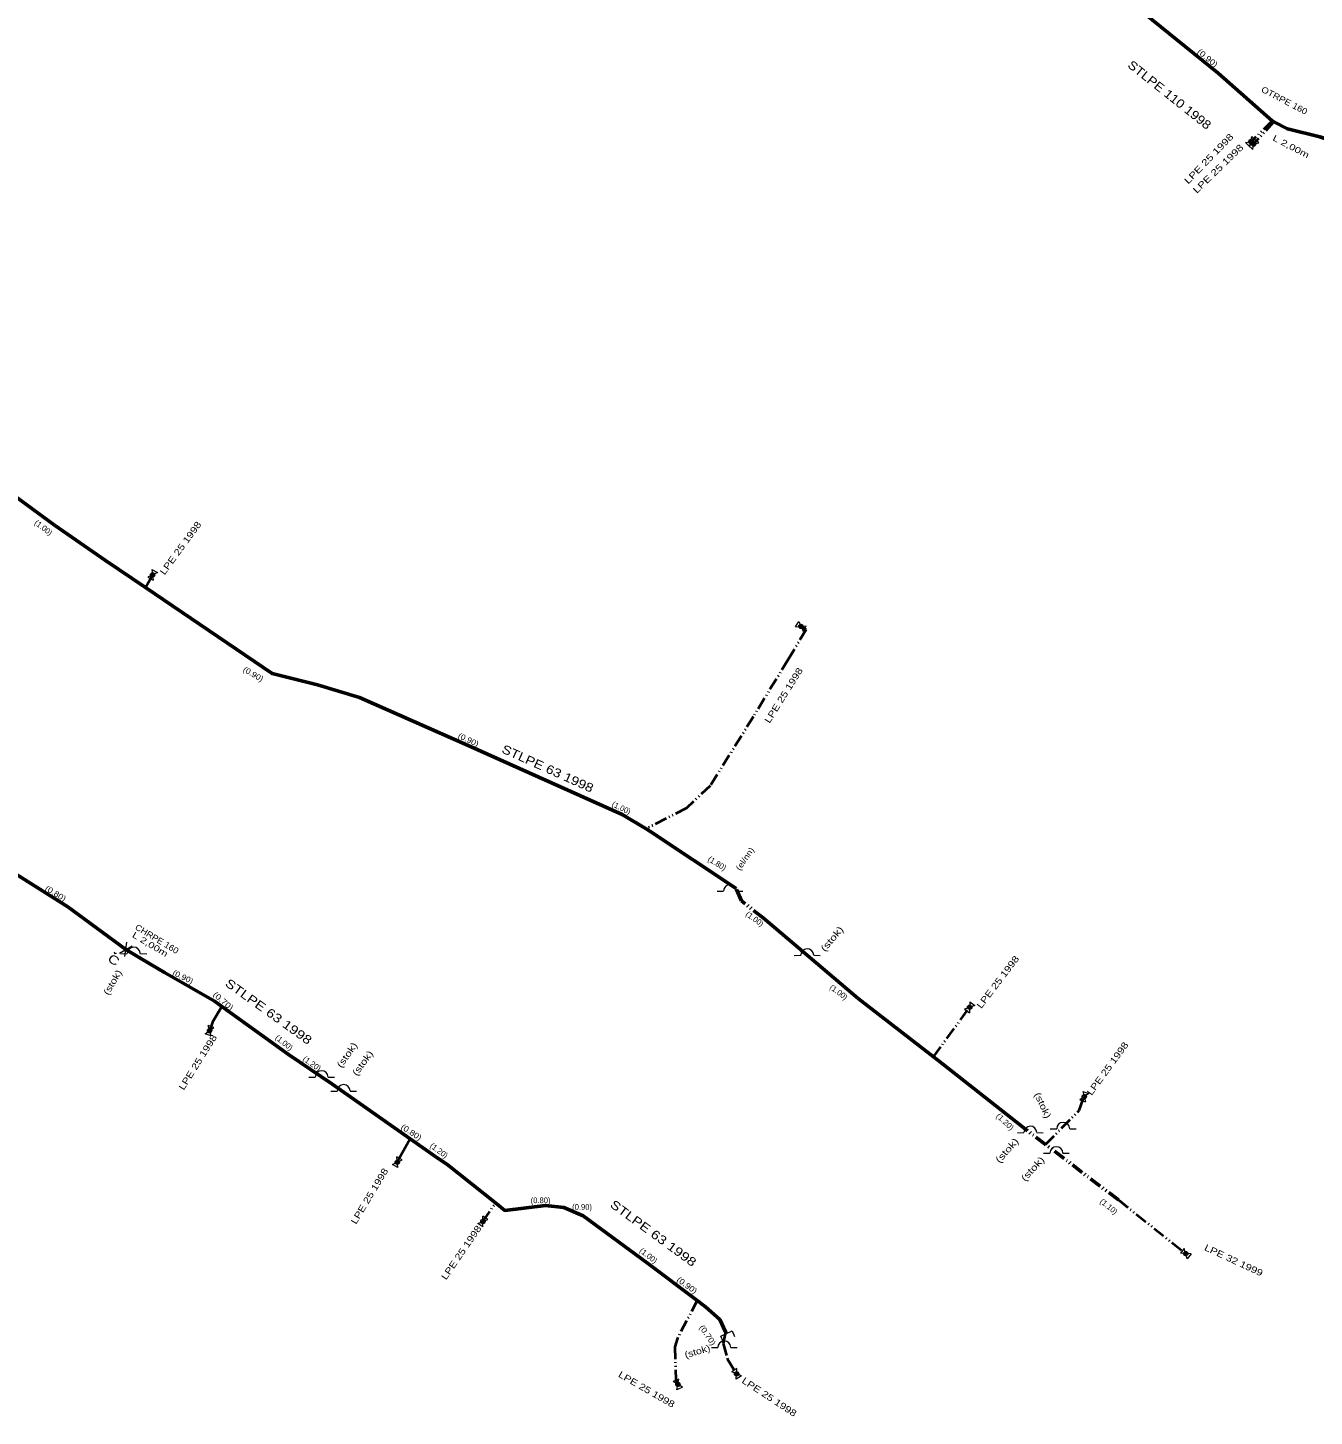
# Model space of a CAD drawing. Extents: x -648036 to -642998, y -1161549 to -1158141.
# Drawn here: x -646338.6 to -646191.3, y -1161129.2 to -1160970.1 of the extents above; entities that cross this region are included whole.
import ezdxf
from ezdxf.enums import TextEntityAlignment as Align

# ---------------------------------------------------------------- set-up
doc = ezdxf.new("R2010")
doc.units = 0
doc.header["$LTSCALE"] = 0.28
doc.linetypes.add('DASH_DOUBLE_DOT', pattern=[9.2, 5, -1.2, 0.3, -1.2, 0.3, -1.2])
for name, color, linetype, lineweight in [('12', 7, 'DASH_DOUBLE_DOT', 40), ('14', 7, 'Continuous', 13), ('15', 7, 'Continuous', 13), ('19', 7, 'Continuous', 13), ('8', 7, 'Continuous', 53)]:
    doc.layers.add(name, color=color, linetype=linetype, lineweight=lineweight)
for name, color, linetype in [('20', 7, 'Continuous'), ('22', 7, 'Continuous'), ('24', 7, 'Continuous'), ('27', 7, 'Continuous'), ('28', 7, 'Continuous')]:
    doc.layers.add(name, color=color, linetype=linetype)

msp = doc.modelspace()

# ---------------------------------------------------------------- linework, layer by layer
at = {"layer": '12'}
for p, q in [((-646196.11, -1160980.79), (-646198.56, -1160983.17)), ((-646195.92, -1160980.89), (-646198.25, -1160983.45)), ((-646325.14, -1161034.26), (-646324.34, -1161032.82)), ((-646234.91, -1161088.02), (-646230.76, -1161082.36)), ((-646213.73, -1161104.44), (-646206.014, -1161110.585)), ((-646286.51, -1161106.9), (-646285.07, -1161104.78))]:
    msp.add_line(p, q, dxfattribs=at)
at = {"layer": '12', "linetype": 'Continuous'}
msp.add_line((-646294.82, -1161097.43), (-646296.31, -1161100.11), dxfattribs=at)
at = {"layer": '12'}
for points in [[(-646250.09, -1161038.71), (-646249.49, -1161039.07), (-646251.54, -1161042.5), (-646255.53, -1161049.04), (-646260.48, -1161056.99), (-646263.2, -1161059.53), (-646267.8, -1161061.91)], [(-646222.06, -1161098.08), (-646218.24, -1161094.19), (-646217.64, -1161092.6)], [(-646261.97, -1161115.97), (-646264.21, -1161120.27), (-646264.52, -1161121.28), (-646264.43, -1161125), (-646264.18, -1161125.57)], [(-646258.71, -1161119.54), (-646258.98, -1161120.89), (-646258.49, -1161122.66), (-646257.45, -1161124.36)]]:
    msp.add_lwpolyline(points, dxfattribs=at)
at = {"layer": '12', "linetype": 'Continuous'}
msp.add_lwpolyline([(-646316.39, -1161082.26), (-646317.47, -1161084.05), (-646317.8, -1161085.05)], dxfattribs=at)
at = {"layer": '14'}
for p, q in [((-646196.11, -1160980.79), (-646194.37, -1160981.71)), ((-646257.52, -1161068.75), (-646267.37, -1161062.17)), ((-646325.67, -1161076.75), (-646327.39, -1161075.72))]:
    msp.add_line(p, q, dxfattribs=at)
at = {"layer": '15'}
for p, q in [((-646199.17, -1160983.266), (-646197.951, -1160983.075)), ((-646198.673, -1160983.777), (-646199.17, -1160983.266)), ((-646198.853, -1160983.583), (-646197.648, -1160983.318)), ((-646198.326, -1160984.062), (-646198.853, -1160983.583)), ((-646198.673, -1160983.777), (-646198.447, -1160982.563)), ((-646197.951, -1160983.075), (-646198.447, -1160982.563)), ((-646198.326, -1160984.062), (-646198.174, -1160982.838)), ((-646197.648, -1160983.318), (-646198.174, -1160982.838)), ((-646323.784, -1161032.552), (-646324.895, -1161033.087)), ((-646324.406, -1161032.207), (-646324.274, -1161033.433)), ((-646324.406, -1161032.207), (-646323.784, -1161032.552)), ((-646324.895, -1161033.087), (-646324.274, -1161033.433)), ((-646250.705, -1161038.756), (-646250.339, -1161038.145)), ((-646250.705, -1161038.756), (-646249.475, -1161038.664)), ((-646250.339, -1161038.145), (-646249.842, -1161039.274)), ((-646249.842, -1161039.274), (-646249.475, -1161038.664)), ((-646259.675, -1161069.035), (-646258.94, -1161069.034)), ((-646257.454, -1161069.034), (-646256.72, -1161069.035)), ((-646328.723, -1161076.01), (-646328.671, -1161076.224)), ((-646328.117, -1161076.14), (-646326.664, -1161075.301)), ((-646327.497, -1161076.552), (-646327.284, -1161074.889)), ((-646328.454, -1161076.18), (-646328.671, -1161076.224)), ((-646327.965, -1161076.215), (-646327.23, -1161076.214)), ((-646325.744, -1161076.214), (-646325.01, -1161076.215)), ((-646250.845, -1161076.405), (-646250.11, -1161076.404)), ((-646248.624, -1161076.404), (-646247.89, -1161076.405)), ((-646230.175, -1161082.164), (-646231.345, -1161082.555)), ((-646230.749, -1161081.743), (-646230.771, -1161082.977)), ((-646230.749, -1161081.743), (-646230.175, -1161082.164)), ((-646231.345, -1161082.555), (-646230.771, -1161082.977)), ((-646318.296, -1161085.417), (-646317.304, -1161084.684)), ((-646317.62, -1161085.64), (-646318.296, -1161085.417)), ((-646317.304, -1161084.684), (-646317.98, -1161084.46)), ((-646317.62, -1161085.64), (-646317.98, -1161084.46)), ((-646306.445, -1161090.365), (-646305.71, -1161090.364)), ((-646304.224, -1161090.364), (-646303.49, -1161090.365)), ((-646303.925, -1161091.965), (-646303.19, -1161091.964)), ((-646301.704, -1161091.964), (-646300.97, -1161091.965)), ((-646217.129, -1161092.254), (-646218.151, -1161092.945)), ((-646218.151, -1161092.945), (-646217.485, -1161093.197)), ((-646217.795, -1161092.003), (-646217.485, -1161093.197)), ((-646217.795, -1161092.003), (-646217.129, -1161092.254)), ((-646221.525, -1161096.285), (-646220.79, -1161096.284)), ((-646219.304, -1161096.284), (-646218.57, -1161096.285)), ((-646225.285, -1161096.725), (-646224.55, -1161096.724)), ((-646223.064, -1161096.724), (-646222.33, -1161096.725)), ((-646296.866, -1161100.378), (-646295.754, -1161099.843)), ((-646295.754, -1161099.843), (-646296.376, -1161099.497)), ((-646296.244, -1161100.723), (-646296.376, -1161099.497)), ((-646222.305, -1161099.075), (-646221.57, -1161099.074)), ((-646220.084, -1161099.074), (-646219.35, -1161099.075)), ((-646296.244, -1161100.723), (-646296.866, -1161100.378)), ((-646287.088, -1161107.117), (-646285.933, -1161106.684)), ((-646286.499, -1161107.517), (-646287.088, -1161107.117)), ((-646285.933, -1161106.684), (-646286.521, -1161106.283)), ((-646286.499, -1161107.517), (-646286.521, -1161106.283)), ((-646206.186, -1161109.993), (-646206.63, -1161110.549)), ((-646205.398, -1161110.621), (-646206.63, -1161110.549)), ((-646205.842, -1161111.177), (-646206.186, -1161109.993)), ((-646205.398, -1161110.621), (-646205.842, -1161111.177)), ((-646260.345, -1161121.355), (-646259.61, -1161121.354)), ((-646258.124, -1161121.354), (-646257.39, -1161121.355)), ((-646264.056, -1161124.966), (-646264.708, -1161125.251)), ((-646263.652, -1161125.889), (-646264.708, -1161125.251)), ((-646264.304, -1161126.175), (-646264.056, -1161124.966)), ((-646257.409, -1161123.745), (-646258.017, -1161124.116)), ((-646256.883, -1161124.604), (-646258.017, -1161124.116)), ((-646257.491, -1161124.976), (-646257.409, -1161123.745)), ((-646256.883, -1161124.604), (-646257.491, -1161124.976)), ((-646263.652, -1161125.889), (-646264.304, -1161126.175))]:
    msp.add_line(p, q, dxfattribs=at)
msp.add_lwpolyline([(-646258.974, -1161120.672), (-646259.264, -1161120.03), (-646257.976, -1161119.45), (-646257.687, -1161120.093)], dxfattribs=at)
for centre in [(-646258.1974, -1161069.0346), (-646326.4874, -1161076.2146), (-646249.3674, -1161076.4046), (-646304.9674, -1161090.3646), (-646302.4474, -1161091.9646), (-646223.8074, -1161096.7246), (-646220.0474, -1161096.2846), (-646220.8274, -1161099.0746), (-646258.8674, -1161121.3546)]:
    msp.add_arc(centre, 0.7431, 1.2748, 179.83951, dxfattribs=at)
at = {"layer": '19'}
for centre, radius in [((-646198.56, -1160983.17), 0.25), ((-646198.56, -1160983.17), 0.17), ((-646198.56, -1160983.17), 0.09), ((-646198.25, -1160983.45), 0.25), ((-646198.25, -1160983.45), 0.17), ((-646198.25, -1160983.45), 0.09), ((-646324.34, -1161032.82), 0.25), ((-646324.34, -1161032.82), 0.17), ((-646324.34, -1161032.82), 0.09), ((-646250.09, -1161038.71), 0.25), ((-646250.09, -1161038.71), 0.17), ((-646250.09, -1161038.71), 0.09), ((-646230.76, -1161082.36), 0.25), ((-646230.76, -1161082.36), 0.17), ((-646230.76, -1161082.36), 0.09), ((-646317.8, -1161085.05), 0.25), ((-646317.8, -1161085.05), 0.17), ((-646317.8, -1161085.05), 0.09), ((-646217.64, -1161092.6), 0.25), ((-646217.64, -1161092.6), 0.17), ((-646217.64, -1161092.6), 0.09), ((-646296.31, -1161100.11), 0.25), ((-646296.31, -1161100.11), 0.17), ((-646296.31, -1161100.11), 0.09), ((-646286.51, -1161106.9), 0.25), ((-646286.51, -1161106.9), 0.17), ((-646286.51, -1161106.9), 0.09), ((-646206.014, -1161110.585), 0.25), ((-646206.014, -1161110.585), 0.17), ((-646206.014, -1161110.585), 0.09), ((-646264.18, -1161125.57), 0.25), ((-646257.45, -1161124.36), 0.25), ((-646257.45, -1161124.36), 0.17), ((-646257.45, -1161124.36), 0.09), ((-646264.18, -1161125.57), 0.17), ((-646264.18, -1161125.57), 0.09)]:
    msp.add_circle(centre, radius, dxfattribs=at)
at = {"layer": '8'}
msp.add_line((-646258.62, -1161119.74), (-646258.71, -1161119.54), dxfattribs=at)
for points in [[(-646196.11, -1160980.79), (-646202.3, -1160975.34), (-646212.64, -1160966.92), (-646217.33, -1160964.33), (-646220.64, -1160962.32), (-646226.9, -1160957.88), (-646230.09, -1160956.67), (-646236.25, -1160953.93), (-646247.6, -1160949.49), (-646251.76, -1160947.85)], [(-646177.44, -1160980.14), (-646188.39, -1160983.38), (-646190.65, -1160982.6), (-646194.37, -1160981.71), (-646195.92, -1160980.89), (-646196.11, -1160980.79)], [(-646325.14, -1161034.26), (-646329.72, -1161031.16), (-646335.55, -1161027.12), (-646345.12, -1161020.14), (-646349.47, -1161016.97), (-646349.88, -1161016.69)], [(-646267.8, -1161061.91), (-646270.56, -1161060.26), (-646288.18, -1161052.37), (-646300.63, -1161046.88), (-646305.44, -1161045.41), (-646310.64, -1161044.12), (-646321, -1161037.07), (-646325.14, -1161034.26)], [(-646327.39, -1161075.72), (-646334.04, -1161070.83), (-646345.33, -1161063.76), (-646352.64, -1161060.17)], [(-646257.52, -1161068.75), (-646267.37, -1161062.17), (-646267.8, -1161061.91)], [(-646234.91, -1161088.02), (-646243.53, -1161081.34), (-646254.42, -1161072.12)], [(-646316.39, -1161082.26), (-646317.26, -1161081.66), (-646322.97, -1161078.36), (-646325.67, -1161076.75), (-646327.39, -1161075.72)], [(-646294.82, -1161097.43), (-646303.81, -1161091.13), (-646308.77, -1161087.78), (-646316.39, -1161082.26)], [(-646224.19, -1161096.46), (-646234.41, -1161088.41), (-646234.91, -1161088.02)], [(-646285.07, -1161104.78), (-646290.65, -1161100.34), (-646291.62, -1161099.67), (-646294.82, -1161097.43)], [(-646261.97, -1161115.97), (-646267.66, -1161111.68), (-646275.03, -1161106.26), (-646277.25, -1161105.29), (-646279.33, -1161105.07), (-646284, -1161105.63), (-646285.07, -1161104.78)], [(-646258.71, -1161119.54), (-646259.36, -1161118.14), (-646261.02, -1161116.69), (-646261.97, -1161115.97)]]:
    msp.add_lwpolyline(points, dxfattribs=at)
at = {"layer": '8', "linetype": 'DASH_DOUBLE_DOT'}
for points in [[(-646254.42, -1161072.12), (-646256.91, -1161070.15), (-646257.52, -1161068.75)], [(-646213.73, -1161104.44), (-646222.06, -1161098.08), (-646224.19, -1161096.46)]]:
    msp.add_lwpolyline(points, dxfattribs=at)

# ---------------------------------------------------------------- texts
at = {"layer": '15', "width": 1.3}
msp.add_text('C', height=1, rotation=327.732, dxfattribs=at).set_placement((-646329.0444, -1161077.3514), align=Align.CENTER)
at = {"layer": '20'}
for s, rotation, width, p in [('STLPE 110 1998', 321.429, 1.15, (-646208.1842, -1160978.2023)), ('STLPE 63 1998', 335.753, 1.2, (-646279.2858, -1161055.4566)), ('STLPE 63 1998', 324.294, 1.25, (-646311.3363, -1161083.2591)), ('STLPE 63 1998', 323.721, 1.25, (-646267.2799, -1161108.6532))]:
    msp.add_text(s, height=1, rotation=rotation, dxfattribs=dict(at, width=width)).set_placement(p, align=Align.CENTER)
at = {"layer": '22'}
for rotation, width, p in [(45.837, 1.3, (-646203.1029, -1160985.3823)), (44.118, 1.3, (-646202.0416, -1160986.5435)), (53.858, 1.25, (-646320.8313, -1161029.9607)), (57.869, 1.25, (-646251.7494, -1161046.8139)), (52.712, 1.25, (-646227.2357, -1161079.6907)), (57.869, 1.25, (-646318.8394, -1161088.8539)), (53.858, 1.25, (-646214.6613, -1161089.6007)), (59.015, 1.25, (-646299.1738, -1161104.1841)), (55.577, 1.25, (-646288.6708, -1161110.674)), (330.024, 1.25, (-646267.9419, -1161126.463)), (326.586, 1.25, (-646253.913, -1161127.3256))]:
    msp.add_text('LPE 25 1998', height=0.75, rotation=rotation, dxfattribs=dict(at, width=width)).set_placement(p, align=Align.CENTER)
at = {"layer": '22', "width": 1.25}
msp.add_text('LPE 32 1999', height=0.75, rotation=335.019, dxfattribs=at).set_placement((-646203.964, -1161110.152))
at = {"layer": '24'}
for s, rotation, width, p in [('OTRPE 160', 332.316, 1.15, (-646194.8781, -1160978.7612)), ('L 2,00m', 332.316, 1.35, (-646194.1181, -1160984.0326)), ('L 2,00m', 328.878, 1.35, (-646324.7954, -1161075.4456)), ('CHRPE 160', 328.878, 1.1, (-646324.0174, -1161074.8253))]:
    msp.add_text(s, height=0.7, rotation=rotation, dxfattribs=dict(at, width=width)).set_placement(p, align=Align.CENTER)
at = {"layer": '27'}
for s, rotation, width, p in [('(0.90)', 320.283, 1.2, (-646203.7227, -1160973.8356)), ('(0.90)', 330.024, 1.1, (-646312.9684, -1161044.4614)), ('(0.90)', 334.607, 1.1, (-646288.3049, -1161052.0017)), ('(el/nn)', 55.577, 1.2, (-646256.2312, -1161065.5332)), ('(0.80)', 328.305, 1.15, (-646335.6133, -1161069.5814)), ('(0.90)', 334.034, 1.1, (-646321.0018, -1161079.1635)), ('(0.70)', 319.138, 1.2, (-646316.4621, -1161081.8925)), ('(1.20)', 316.846, 1.05, (-646226.9313, -1161095.7043)), ('(0.80)', 327.159, 1.15, (-646294.8763, -1161096.9479)), ('(0.90)', 324.294, 1.15, (-646263.3257, -1161114.4755)), ('(0.70)', 304.241, 1.15, (-646261.036, -1161120.1096))]:
    msp.add_text(s, height=0.65, rotation=rotation, dxfattribs=dict(at, width=width)).set_placement(p, align=Align.CENTER)
for s, rotation, p in [('(1.00)', 323.148, (-646337.0289, -1161027.6558)), ('(1.00)', 333.461, (-646270.7937, -1161059.788)), ('(1.80)', 328.305, (-646259.8563, -1161066.1416)), ('(1.00)', 324.294, (-646255.5657, -1161072.4892)), ('(1.00)', 323.721, (-646245.9513, -1161080.8823)), ('(1.00)', 321.429, (-646309.4771, -1161086.6582)), ('(1.20)', 324.867, (-646306.2735, -1161089.0685)), ('(1.20)', 323.148, (-646291.7319, -1161099.0283)), ('(1.10)', 320.856, (-646215.0312, -1161105.4253)), ('(1.00)', 322.002, (-646267.7506, -1161111.0643))]:
    msp.add_text(s, height=0.65, rotation=rotation, dxfattribs=at).set_placement(p, align=Align.CENTER)
for s, p in [('(0.80)', (-646279.9, -1161104.8)), ('(0.90)', (-646275.1495, -1161105.56))]:
    msp.add_text(s, height=0.65, dxfattribs=at).set_placement(p, align=Align.CENTER)
at = {"layer": '28'}
for rotation, width, p in [(49.847, 1.35, (-646246.2452, -1161074.7603)), (59.588, 1.25, (-646328.5968, -1161079.6883)), (55.004, 1.3, (-646301.7586, -1161088.0396)), (53.858, 1.3, (-646299.9757, -1161088.9747)), (295.073, 1.25, (-646222.725, -1161093.7466)), (48.701, 1.35, (-646226.2095, -1161099.007)), (47.555, 1.35, (-646223.2734, -1161101.1231)), (16.616, 1.2, (-646261.8377, -1161122.148))]:
    msp.add_text('(stok)', height=0.75, rotation=rotation, dxfattribs=dict(at, width=width)).set_placement(p, align=Align.CENTER)

doc.saveas('drawing.dxf')
